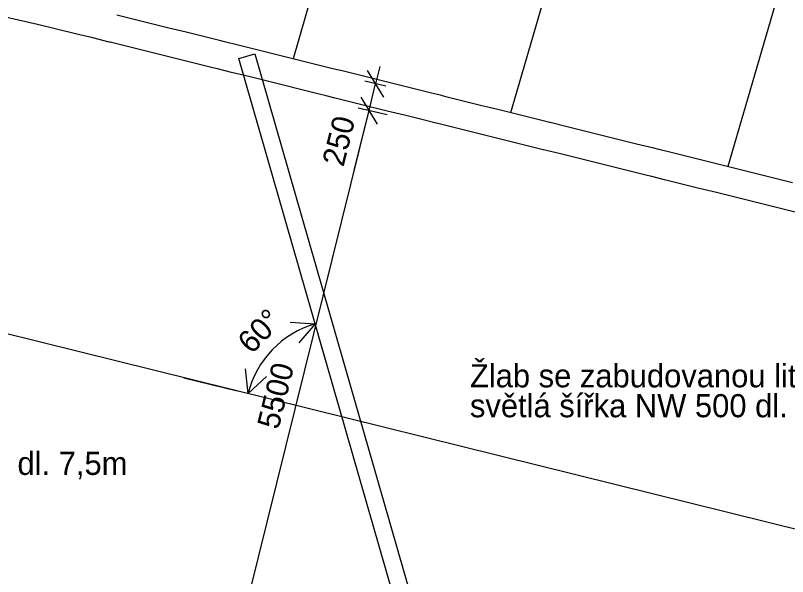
# Model space of a CAD drawing. Extents: x -577013.5 to -576971.5, y -1164310.3 to -1164280.6.
# Drawn here: x -577004.93 to -576998.03, y -1164293.08 to -1164288.07 of the extents above; entities that cross this region are included whole.
import ezdxf

# ---------------------------------------------------------------- set-up
doc = ezdxf.new("R2010")
doc.units = 0
for name, color, linetype in [('5', 7, 'Continuous'), ('Vrstva 1', 7, 'Continuous'), ('Šrafy', 7, 'Continuous')]:
    doc.layers.add(name, color=color, linetype=linetype)

msp = doc.modelspace()

# ---------------------------------------------------------------- linework, layer by layer
for p, q in [((-577004.9004, -1164288.1087), (-577005.0702, -1164288.0699)), ((-577003.8676, -1164288.1028), (-577004.0224, -1164288.0644)), ((-577004.7308, -1164288.1483), (-577004.9004, -1164288.1087)), ((-577003.7127, -1164288.1412), (-577003.8676, -1164288.1028)), ((-577003.5579, -1164288.1795), (-577003.7127, -1164288.1412)), ((-577004.5614, -1164288.1889), (-577004.7308, -1164288.1483)), ((-577004.3926, -1164288.2302), (-577004.5614, -1164288.1889)), ((-577003.403, -1164288.2179), (-577003.5579, -1164288.1795)), ((-577004.2374, -1164288.2687), (-577004.3926, -1164288.2302)), ((-577004.0921, -1164288.3047), (-577004.2374, -1164288.2687)), ((-577003.2482, -1164288.2563), (-577003.403, -1164288.2179)), ((-577003.0933, -1164288.2947), (-577003.2482, -1164288.2563)), ((-577004.0826, -1164288.3071), (-577004.0921, -1164288.3047)), ((-577003.9277, -1164288.3454), (-577004.0826, -1164288.3071)), ((-577003.7729, -1164288.3838), (-577003.9277, -1164288.3454)), ((-577003.0614, -1164288.3026), (-577003.0933, -1164288.2947)), ((-577002.9384, -1164288.333), (-577003.0614, -1164288.3026)), ((-577002.7836, -1164288.3714), (-577002.9384, -1164288.333)), ((-577003.618, -1164288.4222), (-577003.7729, -1164288.3838)), ((-577003.4631, -1164288.4606), (-577003.618, -1164288.4222)), ((-577002.9332, -1164288.451), (-577002.7891, -1164288.4094)), ((-577002.7891, -1164288.4094), (-577000.8944, -1164294.9817)), ((-577002.6287, -1164288.4098), (-577002.7836, -1164288.3714)), ((-577002.4739, -1164288.4482), (-577002.6287, -1164288.4098)), ((-577003.3083, -1164288.4989), (-577003.4631, -1164288.4606)), ((-577001.0385, -1164295.0232), (-577002.9332, -1164288.451)), ((-577002.319, -1164288.4865), (-577002.4739, -1164288.4482)), ((-577002.1642, -1164288.5249), (-577002.319, -1164288.4865)), ((-577003.1534, -1164288.5373), (-577003.3083, -1164288.4989)), ((-577003.1215, -1164288.5452), (-577003.1534, -1164288.5373)), ((-577002.9986, -1164288.5757), (-577003.1215, -1164288.5452)), ((-577002.0907, -1164288.5431), (-577002.1642, -1164288.5249)), ((-577002.0093, -1164288.5633), (-577002.0907, -1164288.5431)), ((-577001.6362, -1164288.7973), (-577001.7814, -1164288.5581)), ((-577001.6704, -1164288.5229), (-577001.7088, -1164288.6777)), ((-577002.8437, -1164288.6141), (-577002.9986, -1164288.5757)), ((-577002.6889, -1164288.6524), (-577002.8437, -1164288.6141)), ((-577001.8545, -1164288.6017), (-577002.0093, -1164288.5633)), ((-577001.6996, -1164288.64), (-577001.8545, -1164288.6017)), ((-577002.534, -1164288.6908), (-577002.6889, -1164288.6524)), ((-577002.3792, -1164288.7292), (-577002.534, -1164288.6908)), ((-577001.6187, -1164288.6991), (-577001.8053, -1164288.6549)), ((-577001.7682, -1164288.9174), (-577001.7088, -1164288.6777)), ((-577001.5447, -1164288.6784), (-577001.6996, -1164288.64)), ((-577001.3899, -1164288.7168), (-577001.5447, -1164288.6784)), ((-577002.2243, -1164288.7676), (-577002.3792, -1164288.7292)), ((-577002.1509, -1164288.7858), (-577002.2243, -1164288.7676)), ((-577001.235, -1164288.7552), (-577001.3899, -1164288.7168)), ((-577001.1201, -1164288.7837), (-577001.235, -1164288.7552)), ((-577002.0694, -1164288.8059), (-577002.1509, -1164288.7858)), ((-577001.9146, -1164288.8443), (-577002.0694, -1164288.8059)), ((-577001.8407, -1164288.7978), (-577001.6956, -1164289.037)), ((-577001.8407, -1164288.7978), (-577001.6956, -1164289.037)), ((-577001.0802, -1164288.7935), (-577001.1201, -1164288.7837)), ((-577000.9253, -1164288.8319), (-577001.0802, -1164288.7935)), ((-577000.7705, -1164288.8703), (-577000.9253, -1164288.8319)), ((-577001.7597, -1164288.8827), (-577001.9146, -1164288.8443)), ((-577001.6063, -1164288.9557), (-577001.8647, -1164288.8945)), ((-577001.6049, -1164288.9211), (-577001.7597, -1164288.8827)), ((-577000.6156, -1164288.9087), (-577000.7705, -1164288.8703)), ((-577003.0856, -1164294.2333), (-577001.7682, -1164288.9174)), ((-577001.9, -1164289.4493), (-577001.7682, -1164288.9174)), ((-577001.45, -1164288.9594), (-577001.6049, -1164288.9211)), ((-577001.2952, -1164288.9978), (-577001.45, -1164288.9594)), ((-577000.4608, -1164288.947), (-577000.6156, -1164288.9087)), ((-577000.3059, -1164288.9854), (-577000.4608, -1164288.947)), ((-577001.1802, -1164289.0263), (-577001.2952, -1164288.9978)), ((-577001.1403, -1164289.0362), (-577001.1802, -1164289.0263)), ((-577000.9855, -1164289.0746), (-577001.1403, -1164289.0362)), ((-577000.151, -1164289.0238), (-577000.3059, -1164288.9854)), ((-577000.1495, -1164289.0242), (-577000.151, -1164289.0238)), ((-576999.9962, -1164289.0622), (-577000.1495, -1164289.0242)), ((-577000.8306, -1164289.113), (-577000.9855, -1164289.0746)), ((-576999.8413, -1164289.1005), (-576999.9962, -1164289.0622)), ((-576999.6865, -1164289.1389), (-576999.8413, -1164289.1005)), ((-577000.6757, -1164289.1513), (-577000.8306, -1164289.113)), ((-577000.5209, -1164289.1897), (-577000.6757, -1164289.1513)), ((-576999.5316, -1164289.1773), (-576999.6865, -1164289.1389)), ((-576999.3768, -1164289.2157), (-576999.5316, -1164289.1773)), ((-577000.366, -1164289.2281), (-577000.5209, -1164289.1897)), ((-577000.2112, -1164289.2665), (-577000.366, -1164289.2281)), ((-576999.2219, -1164289.2541), (-576999.3768, -1164289.2157)), ((-577000.2096, -1164289.2669), (-577000.2112, -1164289.2665)), ((-577000.0563, -1164289.3048), (-577000.2096, -1164289.2669)), ((-576999.9015, -1164289.3432), (-577000.0563, -1164289.3048)), ((-576999.1788, -1164289.2647), (-576999.2219, -1164289.2541)), ((-576999.0671, -1164289.2924), (-576999.1788, -1164289.2647)), ((-576998.9122, -1164289.3308), (-576999.0671, -1164289.2924)), ((-576999.7466, -1164289.3816), (-576999.9015, -1164289.3432)), ((-576999.5918, -1164289.42), (-576999.7466, -1164289.3816)), ((-576998.7574, -1164289.3692), (-576998.9122, -1164289.3308)), ((-576998.6025, -1164289.4076), (-576998.7574, -1164289.3692)), ((-576999.4369, -1164289.4583), (-576999.5918, -1164289.42)), ((-576998.4476, -1164289.4459), (-576998.6025, -1164289.4076)), ((-576998.2928, -1164289.4843), (-576998.4476, -1164289.4459)), ((-576999.2821, -1164289.4967), (-576999.4369, -1164289.4583)), ((-576999.2389, -1164289.5074), (-576999.2821, -1164289.4967)), ((-576999.1272, -1164289.5351), (-576999.2389, -1164289.5074)), ((-576998.2082, -1164289.5053), (-576998.2928, -1164289.4843)), ((-576998.1379, -1164289.5227), (-576998.2082, -1164289.5053)), ((-576997.9831, -1164289.5611), (-576998.1379, -1164289.5227)), ((-576998.9723, -1164289.5735), (-576999.1272, -1164289.5351)), ((-576998.8175, -1164289.6118), (-576998.9723, -1164289.5735)), ((-576998.6626, -1164289.6502), (-576998.8175, -1164289.6118)), ((-576998.5078, -1164289.6886), (-576998.6626, -1164289.6502)), ((-576998.3529, -1164289.727), (-576998.5078, -1164289.6886)), ((-576998.2683, -1164289.7479), (-576998.3529, -1164289.727)), ((-576998.1981, -1164289.7653), (-576998.2683, -1164289.7479)), ((-576998.0432, -1164289.8037), (-576998.1981, -1164289.7653)), ((-576997.8884, -1164289.8421), (-576998.0432, -1164289.8037)), ((-577002.1362, -1164291.2157), (-577002.2218, -1164290.9185)), ((-577003.4238, -1164291.3035), (-577002.9468, -1164291.4217))]:
    msp.add_line(p, q)
for points in [[(-577002.4726, -1164290.8074), (-577002.2495, -1164290.8224), (-577002.3954, -1164290.9919)], [(-577002.6859, -1164291.2936), (-577002.8498, -1164291.4458), (-577002.8732, -1164291.2234)]]:
    msp.add_lwpolyline(points)
msp.add_arc((-577002.0098, -1164291.6539), 0.8653, 106.08153, 166.08153)
at = {"layer": '5'}
msp.add_line((-576992.1353, -1164294.101), (-577005.0541, -1164290.8995), dxfattribs=at)
at = {"layer": 'Šrafy'}
for p, q in [((-577001.7195, -1164285.9595), (-577002.4471, -1164288.4548)), ((-576999.7995, -1164286.5194), (-577000.5042, -1164288.9363)), ((-576997.8794, -1164287.0793), (-576998.5613, -1164289.4178))]:
    msp.add_line(p, q, dxfattribs=at)

# ---------------------------------------------------------------- texts
for s, height, rotation, p in [('250', 0.19841, 76.08153, (-577001.9965, -1164289.4264)), ('60°', 0.2, 46.08153, (-577002.8167, -1164291.1002)), ('5500', 0.19841, 76.08153, (-577002.5782, -1164291.7736))]:
    msp.add_text(s, height=height, rotation=rotation).set_placement(p)
at = {"layer": 'Vrstva 1'}
for s, p in [('Žlab se zabudovanou litinovou hranou BGZ-S V,', (-577000.8661, -1164291.3894)), ('světlá šířka NW 500 dl. 4x 2500 mm , BGZ-S litinový rošt', (-577000.8661, -1164291.6566)), ('Ocelová svodnice dl. 7,5m', (-577007.1681, -1164292.1716))]:
    msp.add_text(s, height=0.206627, dxfattribs=at).set_placement(p)

doc.saveas('drawing.dxf')
